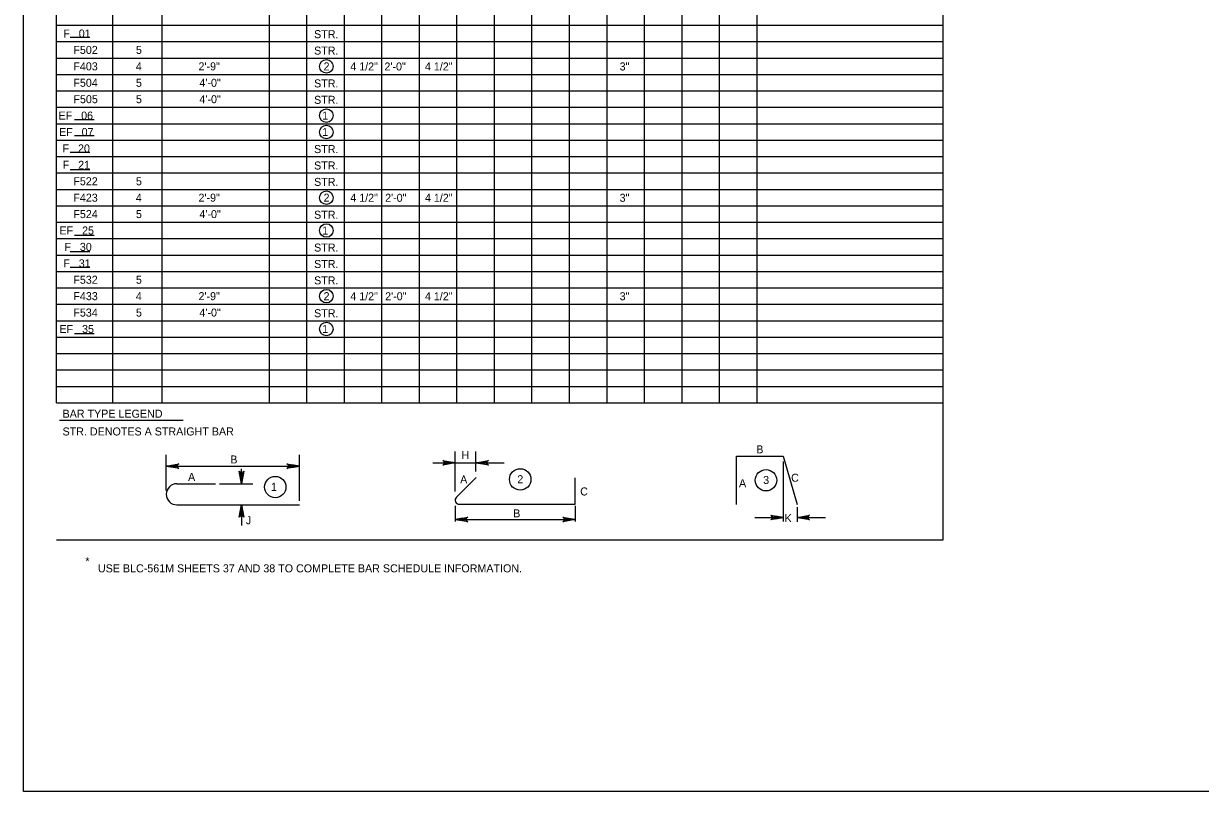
# Model space of a CAD drawing. Extents: x 638340 to 640241, y 295465 to 298435.
# Drawn here: x 639316.5 to 639757.5, y 296668.5 to 296956.2 of the extents above; entities that cross this region are included whole.
import ezdxf

# ---------------------------------------------------------------- set-up
doc = ezdxf.new("R2010")
doc.units = 0
for name, color, linetype in [('2', 7, 'Continuous'), ('3', 7, 'Continuous'), ('4', 7, 'Continuous'), ('6', 7, 'Continuous')]:
    doc.layers.add(name, color=color, linetype=linetype)

msp = doc.modelspace()

# ---------------------------------------------------------------- linework, layer by layer
at = {"layer": '2'}
for p, q in [((639316.46, 296668.46), (639316.46, 297232.46)), ((640102.46, 296668.46), (639316.46, 296668.46))]:
    msp.add_line(p, q, dxfattribs=at)
at = {"layer": '3'}
for p, q in [((639583.68, 296794.08), (639601.12, 296794.08)), ((639583.68, 296775.98), (639583.68, 296794.08)), ((639601.12, 296794.08), (639606.41, 296775.96)), ((639478.71, 296778.73), (639486.03, 296786.06)), ((639523.21, 296776.1), (639523.21, 296786.05)), ((639373.91, 296783.77), (639388.42, 296783.77)), ((639373.91, 296775.86), (639419.83, 296775.86)), ((639479.79, 296776.1), (639523.21, 296776.1))]:
    msp.add_line(p, q, dxfattribs=at)
for centre, radius, start in [((639373.91, 296779.82), 3.95, 90), ((639479.79, 296777.64), 1.54, 135)]:
    msp.add_arc(centre, radius, start, 270, dxfattribs=at)
at = {"layer": '4'}
for p, q in [((639333.9, 296951.11), (639341.31, 296951.11)), ((639335.53, 296920.28), (639342.93, 296920.28)), ((639335.53, 296914.25), (639342.93, 296914.25)), ((639333.9, 296908.1), (639341.31, 296908.1)), ((639333.9, 296901.49), (639341.31, 296901.49)), ((639335.53, 296876.92), (639342.93, 296876.92)), ((639333.9, 296870.77), (639341.31, 296870.77)), ((639333.9, 296864.98), (639341.31, 296864.98)), ((639335.53, 296840.05), (639342.93, 296840.05)), ((639329.93, 296807.59), (639376.28, 296807.59)), ((639369.96, 296781.28), (639369.96, 296794.59)), ((639419.83, 296777.32), (639419.83, 296794.59)), ((639478.26, 296780.91), (639478.26, 296795.88)), ((639486.02, 296788.37), (639486.02, 296795.88)), ((639372.76, 296790.38), (639417.03, 296790.38)), ((639398.18, 296786.58), (639398.18, 296789.38)), ((639469.8, 296791.67), (639496.58, 296791.67)), ((639601.12, 296792.06), (639601.12, 296769.64)), ((639389.88, 296783.77), (639402.39, 296783.77)), ((639395.94, 296775.86), (639402.39, 296775.86)), ((639498.02, 296776.1), (639502.61, 296776.1)), ((639398.18, 296773.06), (639398.18, 296770.25)), ((639478.26, 296775.48), (639478.26, 296769.66)), ((639523.23, 296775.49), (639523.23, 296769.66)), ((639606.41, 296774.95), (639606.41, 296769.56)), ((639398.18, 296770.25), (639398.18, 296768.15)), ((639478.26, 296770.42), (639523.23, 296770.42)), ((639590.55, 296771.1), (639598.9, 296771.1)), ((639609.2, 296771.1), (639617.02, 296771.1))]:
    msp.add_line(p, q, dxfattribs=at)
for points in [[(639369.96, 296790.38), (639374.62, 296791.25), (639374.26, 296791), (639374.07, 296790.69), (639374.02, 296790.38), (639374.07, 296790.06), (639374.26, 296789.75), (639374.62, 296789.5), (639369.96, 296790.38), (639374.26, 296789.75), (639374.07, 296790.06), (639369.96, 296790.38), (639374.02, 296790.38), (639374.07, 296790.69), (639369.96, 296790.38), (639374.26, 296791)], [(639419.83, 296790.38), (639415.17, 296789.5), (639415.53, 296789.75), (639415.72, 296790.06), (639415.77, 296790.38), (639415.72, 296790.69), (639415.53, 296791), (639415.17, 296791.25), (639419.83, 296790.38), (639415.53, 296791), (639415.72, 296790.69), (639419.83, 296790.38), (639415.77, 296790.38), (639415.72, 296790.06), (639419.83, 296790.38), (639415.53, 296789.75)], [(639478.26, 296791.67), (639473.6, 296790.8), (639473.96, 296791.05), (639474.14, 296791.36), (639474.2, 296791.67), (639474.14, 296791.99), (639473.96, 296792.3), (639473.6, 296792.55), (639478.26, 296791.67), (639473.96, 296792.3), (639474.14, 296791.99), (639478.26, 296791.67), (639474.2, 296791.67), (639474.14, 296791.36), (639478.26, 296791.67), (639473.96, 296791.05)], [(639486.02, 296791.67), (639490.68, 296792.55), (639490.32, 296792.3), (639490.13, 296791.99), (639490.08, 296791.67), (639490.13, 296791.36), (639490.32, 296791.05), (639490.68, 296790.8), (639486.02, 296791.67), (639490.32, 296791.05), (639490.13, 296791.36), (639486.02, 296791.67), (639490.08, 296791.67), (639490.13, 296791.99), (639486.02, 296791.67), (639490.32, 296792.3)], [(639398.18, 296783.77), (639397.31, 296788.43), (639397.56, 296788.07), (639397.87, 296787.89), (639398.18, 296787.83), (639398.49, 296787.89), (639398.81, 296788.07), (639399.05, 296788.43), (639398.18, 296783.77), (639398.81, 296788.07), (639398.49, 296787.89), (639398.18, 296783.77), (639398.18, 296787.83), (639397.87, 296787.89), (639398.18, 296783.77), (639397.56, 296788.07)], [(639398.18, 296775.86), (639399.05, 296771.2), (639398.81, 296771.56), (639398.49, 296771.75), (639398.18, 296771.8), (639397.87, 296771.75), (639397.56, 296771.56), (639397.31, 296771.2), (639398.18, 296775.86), (639397.56, 296771.56), (639397.87, 296771.75), (639398.18, 296775.86), (639398.18, 296771.8), (639398.49, 296771.75), (639398.18, 296775.86), (639398.81, 296771.56)], [(639601.13, 296771.1), (639596.47, 296770.22), (639596.83, 296770.47), (639597.01, 296770.78), (639597.07, 296771.1), (639597.01, 296771.41), (639596.83, 296771.72), (639596.47, 296771.97), (639601.13, 296771.1), (639596.83, 296771.72), (639597.01, 296771.41), (639601.13, 296771.1), (639597.07, 296771.1), (639597.01, 296770.78), (639601.13, 296771.1), (639596.83, 296770.47)], [(639606.39, 296771.1), (639611.05, 296771.97), (639610.69, 296771.72), (639610.51, 296771.41), (639610.45, 296771.1), (639610.51, 296770.78), (639610.69, 296770.47), (639611.05, 296770.22), (639606.39, 296771.1), (639610.69, 296770.47), (639610.51, 296770.78), (639606.39, 296771.1), (639610.45, 296771.1), (639610.51, 296771.41), (639606.39, 296771.1), (639610.69, 296771.72)], [(639478.26, 296770.42), (639482.92, 296771.29), (639482.56, 296771.04), (639482.38, 296770.73), (639482.32, 296770.42), (639482.38, 296770.11), (639482.56, 296769.79), (639482.92, 296769.55), (639478.26, 296770.42), (639482.56, 296769.79), (639482.38, 296770.11), (639478.26, 296770.42), (639482.32, 296770.42), (639482.38, 296770.73), (639478.26, 296770.42), (639482.56, 296771.04)], [(639523.23, 296770.42), (639518.57, 296769.55), (639518.93, 296769.79), (639519.11, 296770.11), (639519.17, 296770.42), (639519.11, 296770.73), (639518.93, 296771.04), (639518.57, 296771.29), (639523.23, 296770.42), (639518.93, 296771.04), (639519.11, 296770.73), (639523.23, 296770.42), (639519.17, 296770.42), (639519.11, 296770.11), (639523.23, 296770.42), (639518.93, 296769.79)]]:
    msp.add_lwpolyline(points, dxfattribs=at)
for points in [[(639372.76, 296790.85), (639372.76, 296789.91), (639369.96, 296790.38)], [(639417.03, 296790.85), (639417.03, 296789.91), (639419.83, 296790.38)], [(639397.71, 296786.58), (639398.65, 296786.58), (639398.18, 296783.77)], [(639397.71, 296773.06), (639398.65, 296773.06), (639398.18, 296775.86)], [(639598.33, 296771.57), (639598.33, 296770.63), (639601.13, 296771.1)], [(639609.2, 296771.57), (639609.2, 296770.63), (639606.39, 296771.1)], [(639481.06, 296769.95), (639481.06, 296770.89), (639478.26, 296770.42)], [(639520.42, 296769.95), (639520.42, 296770.89), (639523.23, 296770.42)]]:
    msp.add_lwpolyline(points, close=True, dxfattribs=at)
for centre, radius in [((639429.95, 296940.2), 2.55), ((639429.95, 296921.74), 2.55), ((639429.95, 296915.59), 2.55), ((639429.95, 296890.98), 2.55), ((639429.95, 296878.68), 2.55), ((639429.95, 296854.07), 2.55), ((639429.95, 296841.77), 2.55), ((639502.59, 296785.39), 4.01), ((639594.72, 296785.1), 4.01), ((639410.81, 296782.53), 4.01)]:
    msp.add_circle(centre, radius, dxfattribs=at)
at = {"layer": '6'}
for p, q in [((639328.8, 296814.13), (639328.8, 297232.46)), ((639661.06, 296762.79), (639661.06, 297232.46)), ((639349.89, 296814.13), (639349.89, 297201.7)), ((639368.45, 296814.13), (639368.45, 297201.7)), ((639408.58, 296814.13), (639408.58, 297201.7)), ((639422.64, 296814.13), (639422.64, 297201.7)), ((639436.7, 296814.13), (639436.7, 297201.7)), ((639450.76, 296814.13), (639450.76, 297201.7)), ((639464.82, 296814.13), (639464.82, 297201.7)), ((639478.89, 296814.13), (639478.89, 297201.7)), ((639492.95, 296814.13), (639492.95, 297201.7)), ((639507.01, 296814.13), (639507.01, 297201.7)), ((639521.07, 296814.13), (639521.07, 297201.7)), ((639535.13, 296814.13), (639535.13, 297201.7)), ((639549.19, 296814.13), (639549.19, 297201.7)), ((639563.25, 296814.13), (639563.25, 297201.7)), ((639577.32, 296814.13), (639577.32, 297201.7)), ((639591.38, 296814.13), (639591.38, 297201.7)), ((639328.8, 296955.62), (639661.06, 296955.62)), ((639328.8, 296949.47), (639661.06, 296949.47)), ((639328.8, 296943.32), (639661.06, 296943.32)), ((639328.8, 296937.17), (639661.06, 296937.17)), ((639328.8, 296931.02), (639661.06, 296931.02)), ((639328.8, 296924.86), (639661.06, 296924.86)), ((639328.8, 296918.71), (639661.06, 296918.71)), ((639328.8, 296912.56), (639661.06, 296912.56)), ((639328.8, 296906.41), (639661.06, 296906.41)), ((639328.8, 296900.26), (639661.06, 296900.26)), ((639328.8, 296894.11), (639661.06, 296894.11)), ((639328.8, 296887.95), (639661.06, 296887.95)), ((639328.8, 296881.8), (639661.06, 296881.8)), ((639328.8, 296875.65), (639661.06, 296875.65)), ((639328.8, 296869.5), (639661.06, 296869.5)), ((639328.8, 296863.35), (639661.06, 296863.35)), ((639328.8, 296857.19), (639661.06, 296857.19)), ((639328.8, 296851.04), (639661.06, 296851.04)), ((639328.8, 296844.89), (639661.06, 296844.89)), ((639328.8, 296838.74), (639661.06, 296838.74)), ((639328.8, 296832.59), (639661.06, 296832.59)), ((639328.8, 296826.43), (639661.06, 296826.43)), ((639328.8, 296820.28), (639661.06, 296820.28)), ((639328.8, 296814.13), (639661.06, 296814.13)), ((639328.8, 296762.79), (639661.06, 296762.79))]:
    msp.add_line(p, q, dxfattribs=at)

# ---------------------------------------------------------------- texts
at = {"layer": '4'}
for s, height, p in [('F   01', 3, (639331.36, 296951.01)), ('STR.', 3, (639425.35, 296950.76)), ('F502', 3, (639335.13, 296944.86)), ('5', 3, (639358.59, 296944.86)), ('STR.', 3, (639425.35, 296944.61)), ('F403', 3, (639335.12, 296938.71)), ('4', 3, (639358.55, 296938.71)), ('2\'-9"', 3, (639382.03, 296938.71)), ('2', 3, (639428.9, 296938.69)), ('4 1/2"', 3, (639438.91, 296938.66)), ('2\'-0"', 2.996, (639451.73, 296938.66)), ('4 1/2"', 3, (639466.89, 296938.66)), ('3"', 3, (639539.86, 296938.66)), ('F504', 3, (639335.13, 296932.55)), ('5', 3, (639358.59, 296932.55)), ('4\'-0"', 3, (639382.38, 296932.55)), ('STR.', 3, (639425.35, 296932.31)), ('F505', 3, (639335.16, 296926.4)), ('5', 3, (639358.59, 296926.4)), ('4\'-0"', 3, (639382.38, 296926.4)), ('STR.', 3, (639425.35, 296926.16)), ('EF   06', 3, (639329.57, 296920.25)), ('1', 3, (639428.37, 296920.24)), ('EF   07', 3, (639329.76, 296914.1)), ('1', 3, (639428.37, 296914.09)), ('F   20', 3, (639331.08, 296907.95)), ('STR.', 3, (639425.35, 296907.7)), ('F   21', 3, (639331.13, 296901.8)), ('STR.', 3, (639425.35, 296901.55)), ('F522', 3, (639335.11, 296895.64)), ('5', 3, (639358.59, 296895.64)), ('STR.', 3, (639425.35, 296895.4)), ('F423', 3, (639335.12, 296889.49)), ('4', 3, (639358.55, 296889.49)), ('2\'-9"', 3, (639382.03, 296889.49)), ('2', 3, (639428.9, 296889.48)), ('4 1/2"', 3, (639438.91, 296889.45)), ('2\'-0"', 2.996, (639451.97, 296889.45)), ('4 1/2"', 3, (639466.89, 296889.45)), ('3"', 3, (639539.86, 296889.45)), ('F524', 3, (639335.13, 296883.34)), ('5', 3, (639358.59, 296883.34)), ('4\'-0"', 3, (639382.38, 296883.34)), ('STR.', 3, (639425.35, 296883.09)), ('EF   25', 3, (639329.92, 296877.19)), ('1', 3, (639428.37, 296877.18)), ('F   30', 3, (639331.78, 296871.04)), ('STR.', 3, (639425.35, 296870.79)), ('F   31', 3, (639331.36, 296864.88)), ('STR.', 3, (639425.35, 296864.64)), ('F532', 3, (639335.11, 296858.73)), ('5', 3, (639358.59, 296858.73)), ('STR.', 3, (639425.35, 296858.49)), ('F433', 3, (639335.12, 296852.58)), ('4', 3, (639358.55, 296852.58)), ('2\'-9"', 3, (639382.03, 296852.58)), ('2', 3, (639428.9, 296852.57)), ('4 1/2"', 3, (639438.91, 296852.54)), ('2\'-0"', 2.996, (639451.99, 296852.54)), ('4 1/2"', 3, (639466.89, 296852.54)), ('3"', 3, (639539.86, 296852.54)), ('F534', 3, (639335.13, 296846.43)), ('5', 3, (639358.59, 296846.43)), ('4\'-0"', 3, (639382.38, 296846.43)), ('STR.', 3, (639425.35, 296846.18)), ('EF   35', 3, (639329.92, 296840.28)), ('1', 3, (639428.37, 296840.27)), ('BAR TYPE LEGEND', 3.0001, (639331.08, 296808.53)), ('STR. DENOTES A STRAIGHT BAR', 3.0001, (639331.08, 296801.87)), ('B', 3, (639591.08, 296795.16)), ('B', 3, (639393.95, 296791.37)), ('H', 3, (639480.57, 296792.99)), ('A', 3, (639378.12, 296784.82)), ('A', 3, (639480.09, 296783.89)), ('2', 3, (639501.51, 296783.99)), ('A', 3, (639584.6, 296782.49)), ('3', 3, (639593.65, 296783.69)), ('C', 3, (639604.13, 296784.54)), ('1', 3, (639409.19, 296781.12)), ('C', 3, (639525.08, 296779.39)), ('J', 3, (639399.78, 296768.6)), ('B', 3, (639499.98, 296771.19)), ('K', 3, (639601.69, 296769.38)), ('*', 3, (639339.62, 296753.24)), ('USE BLC-561M SHEETS 37 AND 38 TO COMPLETE BAR SCHEDULE INFORMATION.', 3.0001, (639344.34, 296750.57))]:
    msp.add_text(s, height=height, dxfattribs=at).set_placement(p)

doc.saveas('drawing.dxf')
